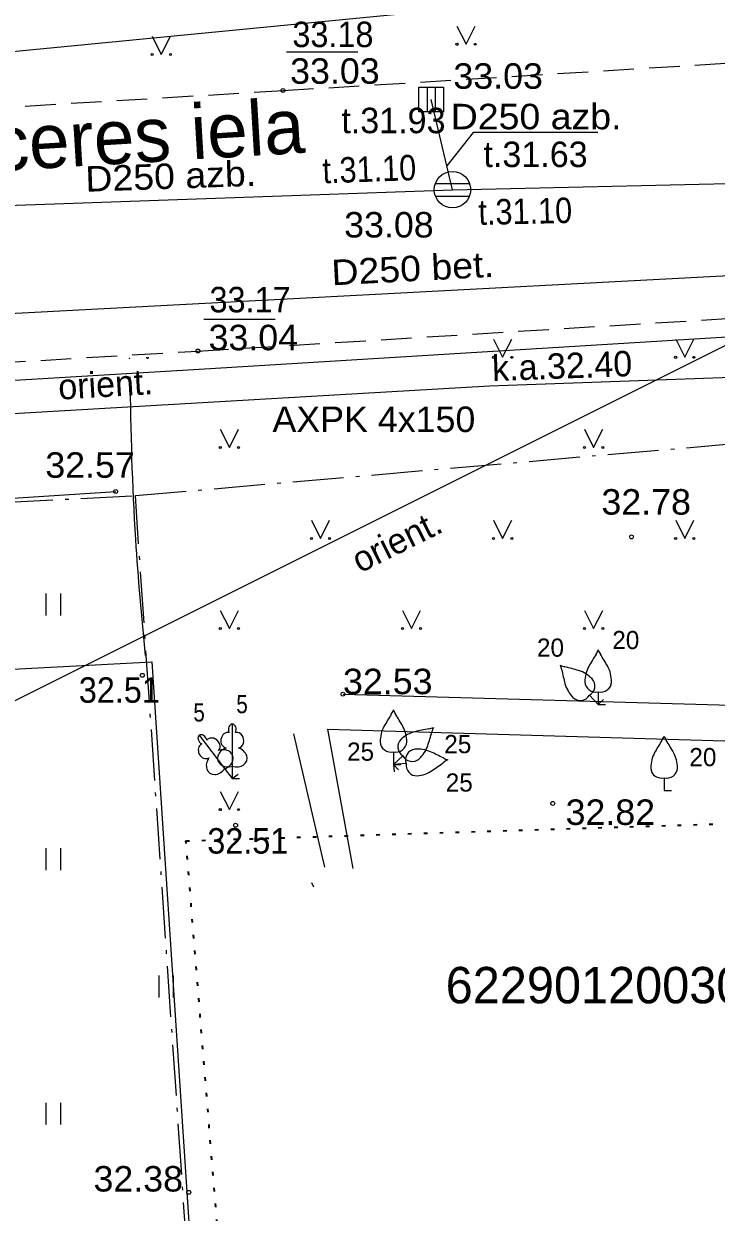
# Model space of a CAD drawing. Extents: x 380758 to 381729, y 283236 to 283533.
# Drawn here: x 381428.59 to 381447.62, y 283330.66 to 283363.33 of the extents above; entities that cross this region are included whole.
import ezdxf
from ezdxf.enums import TextEntityAlignment as Align

# ---------------------------------------------------------------- set-up
doc = ezdxf.new("R2010")
doc.units = 0
doc.header["$LTSCALE"] = 0.28
for name, pattern in [('DOT_DASHED', [7.7, 5, -1.2, 0.3, -1.2]), ('DOTTED', [1.5, 0.3, -1.2]), ('MEDIUM_DASHED', [4.5, 3, -1.5])]:
    doc.linetypes.add(name, pattern=pattern)
for name, color, linetype, lineweight in [('1', 7, 'Continuous', 13), ('11', 7, 'Continuous', 13), ('17', 7, 'Continuous', 13), ('21', 7, 'Continuous', 25), ('23', 7, 'Continuous', 13), ('25', 7, 'DOTTED', 35), ('29', 7, 'DOT_DASHED', 25), ('35', 7, 'Continuous', 13), ('37', 7, 'MEDIUM_DASHED', 13), ('45', 7, 'Continuous', 13), ('47', 7, 'Continuous', 13), ('48', 7, 'Continuous', 25), ('58', 7, 'Continuous', 25), ('7', 7, 'Continuous', 13), ('9', 7, 'Continuous', 13)]:
    doc.layers.add(name, color=color, linetype=linetype, lineweight=lineweight)
doc.layers.add('56', color=7, linetype='Continuous')
doc.layers.add('59', color=7, linetype='Continuous')

msp = doc.modelspace()

# ---------------------------------------------------------------- linework, layer by layer
at = {"layer": '1'}
for p, q in [((381395.278, 283348.094), (381431.118, 283350.472)), ((381437.365, 283344.9), (381450.104, 283344.543)), ((381444.134, 283344.869), (381444.378, 283344.616)), ((381444.378, 283344.968), (381444.378, 283344.616)), ((381444.378, 283344.616), (381444.522, 283344.755)), ((381444.378, 283344.616), (381444.578, 283344.616)), ((381434.323, 283344.078), (381434.323, 283342.925)), ((381433.413, 283343.77), (381434.112, 283342.854)), ((381434.413, 283343.846), (381434.412, 283343.847)), ((381436.864, 283340.147), (381436.015, 283343.807)), ((381433.625, 283343.64), (381433.623, 283343.64)), ((381438.751, 283343.319), (381438.751, 283342.967)), ((381439.009, 283343.206), (381438.751, 283342.967)), ((381434.112, 283342.854), (381434.323, 283342.578)), ((381434.323, 283342.925), (381434.323, 283342.578)), ((381439.102, 283342.998), (381438.751, 283342.967)), ((381438.751, 283342.967), (381438.951, 283342.967)), ((381438.751, 283342.967), (381438.887, 283342.82)), ((381438.751, 283342.967), (381438.768, 283342.768)), ((381434.323, 283342.578), (381434.482, 283342.699)), ((381434.323, 283342.578), (381434.523, 283342.578)), ((381446.188, 283342.601), (381446.188, 283342.249)), ((381446.188, 283342.249), (381446.388, 283342.249))]:
    msp.add_line(p, q, dxfattribs=at)
for centre, radius, start, end in [((381443.9608, 283346.2539), 0.4394, 324.38368, 341.71196), ((381444.7952, 283346.2539), 0.4394, 198.28804, 215.61632), ((381457.0028, 283338.22), 14.8796, 148.48442, 149.99014), ((381431.7532, 283338.22), 14.8796, 30.00986, 31.51558), ((381443.5417, 283346.0848), 0.4394, 242.23488, 259.56316), ((381442.941, 283345.5057), 0.4394, 8.33052, 25.6588), ((381457.9064, 283348.7725), 14.8796, 192.43126, 193.93698), ((381439.7271, 283331.2495), 14.8796, 73.9567, 75.46242), ((381443.5669, 283344.7018), 0.8904, 44.033, 72.18982), ((381444.9024, 283345.2407), 0.8904, 151.75702, 179.91384), ((381443.8536, 283345.2407), 0.8904, 0.08616, 28.24298), ((381444.322, 283345.4297), 0.8904, 195.70387, 223.86068), ((381444.3016, 283345.2475), 0.2897, 181.07816, 285.2823), ((381443.9948, 283345.1236), 0.2897, 298.66454, 42.86868), ((381444.4544, 283345.2475), 0.2897, 254.7177, 358.92184), ((381443.8848, 283345.0176), 0.2897, 225.025, 329.22914), ((381438.3338, 283344.6049), 0.4394, 324.38368, 341.71196), ((381439.1682, 283344.6049), 0.4394, 198.28804, 215.61632), ((381451.3758, 283336.571), 14.8796, 148.48442, 149.99014), ((381426.1262, 283336.571), 14.8796, 30.00986, 31.51558), ((381439.2754, 283343.5917), 0.8904, 151.75702, 179.91384), ((381439.5656, 283343.0069), 0.8904, 104.57239, 132.7292), ((381438.2266, 283343.5917), 0.8904, 0.08616, 28.24298), ((381442.6395, 283329.3591), 14.8796, 101.29978, 102.8055), ((381425.4789, 283347.8809), 14.8796, 342.82522, 344.33094), ((381439.6689, 283344.3862), 0.4394, 277.19904, 294.52732), ((381440.236, 283343.7741), 0.4394, 151.1034, 168.43168), ((381445.7708, 283343.8869), 0.4394, 324.38368, 341.71196), ((381446.6052, 283343.8869), 0.4394, 198.28804, 215.61632), ((381438.6746, 283343.5985), 0.2897, 181.07816, 285.2823), ((381438.8274, 283343.5985), 0.2897, 254.7177, 358.92184), ((381439.1623, 283343.4522), 0.2897, 133.89352, 238.09766), ((381438.8528, 283343.7762), 0.8904, 312.90152, 341.05834), ((381458.8128, 283335.853), 14.8796, 148.48442, 149.99014), ((381433.5632, 283335.853), 14.8796, 30.00986, 31.51558), ((381439.2661, 283343.3401), 0.2897, 207.53306, 311.7372), ((381439.3734, 283343.0979), 0.2897, 96.0598, 200.26394), ((381439.4188, 283342.4988), 0.8904, 66.73867, 94.89549), ((381433.4754, 283329.8345), 14.8796, 63.46607, 64.97178), ((381440.3465, 283343.5248), 0.4394, 239.36532, 256.69361), ((381440.4189, 283342.6936), 0.4394, 113.26968, 130.59797), ((381446.7124, 283342.8737), 0.8904, 151.75702, 179.91384), ((381445.6636, 283342.8737), 0.8904, 0.08616, 28.24298), ((381439.3867, 283342.9458), 0.2897, 169.69934, 273.90349), ((381439.3278, 283343.5436), 0.8904, 275.0678, 303.22462), ((381431.2829, 283354.9887), 14.8796, 304.99151, 306.49722), ((381446.1116, 283342.8805), 0.2897, 181.07816, 285.2823), ((381446.2644, 283342.8805), 0.2897, 254.7177, 358.92184)]:
    msp.add_arc(centre, radius, start, end, dxfattribs=at)
for centre, major_axis, ratio, start_param, end_param in [((381434.3234, 283343.9281), (0, -0.1499), 0.707107, 3.1453698, 5.2874846), ((381434.3226, 283343.9281), (0, -0.1499), 0.707107, 0.9957007, 3.1378155), ((381433.5038, 283343.6511), (0.091, -0.1192), 0.707107, 3.1453698, 5.2874846), ((381433.5032, 283343.6507), (0.091, -0.1192), 0.707107, 0.9957007, 3.1378155), ((381434.1947, 283343.6332), (-0.0387, -0.2124), 0.861323, 3.1415927, 6.2831853), ((381434.4513, 283343.6332), (0.0387, -0.2124), 0.861323, 6.2831853, 9.424778), ((381433.5805, 283343.3387), (0.0981, -0.1923), 0.861323, 3.1415927, 6.2831853), ((381433.7844, 283343.4944), (0.1597, -0.1453), 0.861323, 0, 3.1415927), ((381434.2334, 283343.1709), (0.3068, 0.0951), 0.814445, 1.5707963, 4.7520146), ((381434.4126, 283343.1709), (-0.3068, 0.0951), 0.814445, 1.5311707, 4.712389), ((381433.8919, 283342.9948), (0.1861, 0.2618), 0.814445, 1.5707963, 4.7520146), ((381434.0343, 283343.1036), (-0.3016, -0.1106), 0.814445, 1.5311707, 4.712389)]:
    msp.add_ellipse(centre, major_axis=major_axis, ratio=ratio, start_param=start_param, end_param=end_param, dxfattribs=at)
at = {"layer": '11'}
for p, q in [((381440.373, 283358.767), (381439.786, 283361.244)), ((381440.373, 283358.767), (381464.998, 283359.333)), ((381419.973, 283358.043), (381440.373, 283358.767))]:
    msp.add_line(p, q, dxfattribs=at)
msp.add_lwpolyline([(381444.365, 283360.339), (381440.943, 283360.339), (381440.218, 283359.422)], dxfattribs=at)
at = {"layer": '17'}
msp.add_lwpolyline([(381389.117, 283351.081), (381395.098, 283351.508), (381402.928, 283352.014), (381416.512, 283352.829), (381433.409, 283353.834), (381450.312, 283354.874), (381458.856, 283355.374)], dxfattribs=at)
at = {"layer": '21'}
msp.add_spline([(381431.504, 283353.627), (381431.66, 283349.154), (381431.932, 283345.966)], degree=3, dxfattribs=at)
at = {"layer": '23'}
for p, q in [((381429.209, 283347.066), (381429.209, 283347.666)), ((381429.609, 283347.066), (381429.609, 283347.666)), ((381429.209, 283340.066), (381429.209, 283340.666)), ((381429.609, 283340.066), (381429.609, 283340.666)), ((381436.498, 283339.726), (381436.557, 283339.606)), ((381432.309, 283336.566), (381432.309, 283337.166)), ((381432.709, 283336.566), (381432.709, 283337.166)), ((381429.209, 283333.066), (381429.209, 283333.666)), ((381429.609, 283333.066), (381429.609, 283333.666))]:
    msp.add_line(p, q, dxfattribs=at)
for points in [[(381440.497, 283363.265), (381440.747, 283362.765), (381440.997, 283363.265)], [(381432.122, 283362.988), (381432.372, 283362.488), (381432.622, 283362.988)], [(381441.502, 283354.66), (381441.752, 283354.16), (381442.002, 283354.66)], [(381446.506, 283354.66), (381446.756, 283354.16), (381447.006, 283354.66)], [(381433.994, 283352.182), (381434.244, 283351.682), (381434.494, 283352.182)], [(381444.002, 283352.182), (381444.252, 283351.682), (381444.502, 283352.182)], [(381436.498, 283349.682), (381436.748, 283349.182), (381436.998, 283349.682)], [(381441.502, 283349.682), (381441.752, 283349.182), (381442.002, 283349.682)], [(381446.506, 283349.682), (381446.756, 283349.182), (381447.006, 283349.682)], [(381433.994, 283347.204), (381434.244, 283346.704), (381434.494, 283347.204)], [(381438.998, 283347.204), (381439.248, 283346.704), (381439.498, 283347.204)], [(381444.002, 283347.204), (381444.252, 283346.704), (381444.502, 283347.204)], [(381433.994, 283342.226), (381434.244, 283341.726), (381434.494, 283342.226)]]:
    msp.add_lwpolyline(points, dxfattribs=at)
for centre, radius in [((381440.4971, 283362.7646), 0.028), ((381440.9971, 283362.7646), 0.0263), ((381432.1217, 283362.4871), 0.028), ((381432.6217, 283362.4871), 0.0263), ((381441.5013, 283354.1597), 0.028), ((381442.0013, 283354.1597), 0.0263), ((381446.5053, 283354.1597), 0.028), ((381447.0053, 283354.1597), 0.0263), ((381433.9933, 283351.6817), 0.028), ((381434.4933, 283351.6817), 0.0263), ((381444.0013, 283351.6817), 0.028), ((381444.5013, 283351.6817), 0.0263), ((381436.4973, 283349.1817), 0.028), ((381436.9973, 283349.1817), 0.0263), ((381441.5013, 283349.1817), 0.028), ((381442.0013, 283349.1817), 0.0263), ((381446.5053, 283349.1817), 0.028), ((381447.0053, 283349.1817), 0.0263), ((381433.9933, 283346.7037), 0.028), ((381434.4933, 283346.7037), 0.0263), ((381438.9973, 283346.7037), 0.028), ((381439.4973, 283346.7037), 0.0263), ((381444.0013, 283346.7037), 0.028), ((381444.5013, 283346.7037), 0.0263), ((381433.9933, 283341.7257), 0.028), ((381434.4933, 283341.7257), 0.0263)]:
    msp.add_circle(centre, radius, dxfattribs=at)
for centre, radius, start, end in [((381431.4933, 283354.1597), 0.028, 250.28372, 297.16961), ((381431.9933, 283354.1597), 0.0263, 168.72415, 18.72918)]:
    msp.add_arc(centre, radius, start, end, dxfattribs=at)
at = {"layer": '25'}
msp.add_lwpolyline([(381358.23, 283334.462), (381389.309, 283326.777), (381400.12, 283303.606), (381400.55, 283302.499), (381429.749, 283306.005), (381435.528, 283310.373), (381433.049, 283340.868), (381456.224, 283341.607), (381495.519, 283344.123), (381528.407, 283346.153)], dxfattribs=at)
at = {"layer": '29'}
msp.add_line((381435.004, 283301.359), (381431.659, 283350.36), dxfattribs=at)
for points in [[(381431.659, 283350.36), (381480.851, 283354.634), (381480.88, 283354.179)], [(381380.81, 283334.546), (381395.244, 283334.434), (381395.42, 283344.863), (381381.932, 283344.092), (381382.445, 283347.789), (381431.659, 283350.36)]]:
    msp.add_lwpolyline(points, dxfattribs=at)
at = {"layer": '35'}
for points in [[(381401.803, 283342.89), (381405.92, 283344.402), (381432.116, 283345.788), (381434.467, 283310.113), (381430.26, 283307.951)], [(381437.645, 283340.108), (381436.944, 283343.938), (381451.273, 283343.52)]]:
    msp.add_lwpolyline(points, dxfattribs=at)
at = {"layer": '37', "lineweight": 25}
for points in [[(381309.426, 283365.712), (381316.201, 283360.727), (381318.377, 283359.189), (381320.24, 283357.84), (381330.826, 283355.148), (381345.75, 283356.042), (381361.347, 283356.997), (381379.416, 283358.112), (381395.576, 283359.052), (381419.83, 283360.537), (381435.717, 283361.494), (381453.632, 283362.598)], [(381389.081, 283351.58), (381395.064, 283352.007), (381402.897, 283352.513), (381416.482, 283353.328), (381433.379, 283354.333), (381450.282, 283355.373), (381458.878, 283355.876)]]:
    msp.add_lwpolyline(points, dxfattribs=at)
at = {"layer": '45'}
msp.add_lwpolyline([(381392.214, 283360.116), (381421.765, 283361.936), (381446.512, 283364.342), (381453.262, 283365.948)], dxfattribs=at)
at = {"layer": '47'}
msp.add_lwpolyline([(381327.333, 283349.98), (381423.16, 283355.103), (381470.505, 283357.6)], dxfattribs=at)
at = {"layer": '48'}
for p, q in [((381439.673, 283361.582), (381439.673, 283360.907)), ((381439.898, 283361.582), (381439.898, 283360.907)), ((381439.905, 283358.942), (381440.841, 283358.942)), ((381439.905, 283358.592), (381440.841, 283358.592))]:
    msp.add_line(p, q, dxfattribs=at)
msp.add_lwpolyline([(381439.448, 283361.582), (381440.123, 283361.582), (381440.123, 283360.907), (381439.448, 283360.907)], close=True, dxfattribs=at)
msp.add_circle((381440.373, 283358.767), 0.5, dxfattribs=at)
at = {"layer": '58', "lineweight": 13}
for p, q in [((381435.815, 283362.556), (381437.773, 283362.556)), ((381433.539, 283355.208), (381435.497, 283355.208))]:
    msp.add_line(p, q, dxfattribs=at)
at = {"layer": '58'}
for centre in [(381435.717, 283361.4941), (381433.379, 283354.3331), (381431.118, 283350.4721), (381445.291, 283349.2231), (381431.851, 283345.4191), (381437.365, 283344.9001), (381443.128, 283341.8961), (381434.414, 283341.2961), (381433.126, 283331.2051)]:
    msp.add_circle(centre, 0.0534, dxfattribs=at)
at = {"layer": '7'}
msp.add_lwpolyline([(381460.834, 283354.062), (381441.392, 283353.365), (381424.187, 283352.367), (381396.884, 283351.089)], dxfattribs=at)
at = {"layer": '9'}
msp.add_line((381505.481, 283383.309), (381409.418, 283335.25), dxfattribs=at)

# ---------------------------------------------------------------- texts
at = {"layer": '1'}
for s, p in [('20', (381442.694, 283345.93)), ('20', (381444.764, 283346.138)), ('25', (381440.147, 283343.278)), ('25', (381437.476, 283343.071)), ('20', (381446.882, 283342.92)), ('25', (381440.188, 283342.222))]:
    msp.add_text(s, height=0.5, dxfattribs=at).set_placement(p)
at = {"layer": '1', "width": 0.85}
for p in [(381434.432, 283344.377), (381433.252, 283344.149)]:
    msp.add_text('5', height=0.5, dxfattribs=at).set_placement(p)
at = {"layer": '11', "width": 1.1}
msp.add_text('D250 azb.', height=0.7, dxfattribs=at).set_placement((381442.6715, 283360.429), align=Align.CENTER)
at = {"layer": '11'}
for s, p in [('t.31.93', (381438.75, 283360.321)), ('t.31.63', (381442.656, 283359.39))]:
    msp.add_text(s, height=0.7, dxfattribs=at).set_placement(p, align=Align.CENTER)
for s, rotation, width, p in [('D250 azb.', 2.033, 1.1, (381432.6426, 283358.7931)), ('t.31.10', 2.033, 0.9, (381438.1001, 283358.9861)), ('t.31.10', 1.317, 0.9, (381442.3805, 283357.8268))]:
    msp.add_text(s, height=0.7, rotation=rotation, dxfattribs=dict(at, width=width)).set_placement(p, align=Align.CENTER)
at = {"layer": '17'}
msp.add_text('orient.', height=0.7, rotation=3.404, dxfattribs=at).set_placement((381430.8587, 283353.0716), align=Align.CENTER)
at = {"layer": '47', "width": 1.1}
msp.add_text('D250 bet.', height=0.7, rotation=3.019, dxfattribs=at).set_placement((381439.2956, 283356.255), align=Align.CENTER)
at = {"layer": '48', "width": 1.05}
for s, p in [('33.03', (381440.398, 283361.543)), ('33.08', (381437.397, 283357.454))]:
    msp.add_text(s, height=0.7, dxfattribs=at).set_placement(p)
at = {"layer": '56'}
msp.add_text('Cieceres iela', height=1.5, rotation=3.433, dxfattribs=at).set_placement((381424.769, 283359.092))
at = {"layer": '58'}
for s, width, p in [('33.18', 0.95, (381435.975, 283362.687)), ('33.03', 1.05, (381435.912, 283361.68)), ('33.17', 0.95, (381433.697, 283355.396)), ('33.04', 1.05, (381433.671, 283354.354)), ('32.57', 1.05, (381429.185, 283350.849)), ('32.78', 1.05, (381444.466, 283349.836)), ('32.53', 1.05, (381437.365, 283344.9)), ('32.51', 0.95, (381430.106, 283344.664)), ('32.82', 1.05, (381443.481, 283341.306)), ('32.51', 0.95, (381433.636, 283340.517)), ('32.38', 1.05, (381430.509, 283331.228))]:
    msp.add_text(s, height=0.7, dxfattribs=dict(at, width=width)).set_placement(p)
at = {"layer": '59'}
msp.add_text('62290120030', height=1, dxfattribs=at).set_placement((381440.186, 283336.402))
at = {"layer": '7'}
msp.add_text('k.a.32.40', height=0.7, rotation=2.053, dxfattribs=at).set_placement((381441.474, 283353.507))
at = {"layer": '7', "width": 1.05}
msp.add_text('AXPK 4x150', height=0.7, dxfattribs=at).set_placement((381435.427, 283352.107))
at = {"layer": '9'}
msp.add_text('orient.', height=0.7, rotation=26.578, dxfattribs=at).set_placement((381438.9954, 283348.7986), align=Align.CENTER)

doc.saveas('drawing.dxf')
